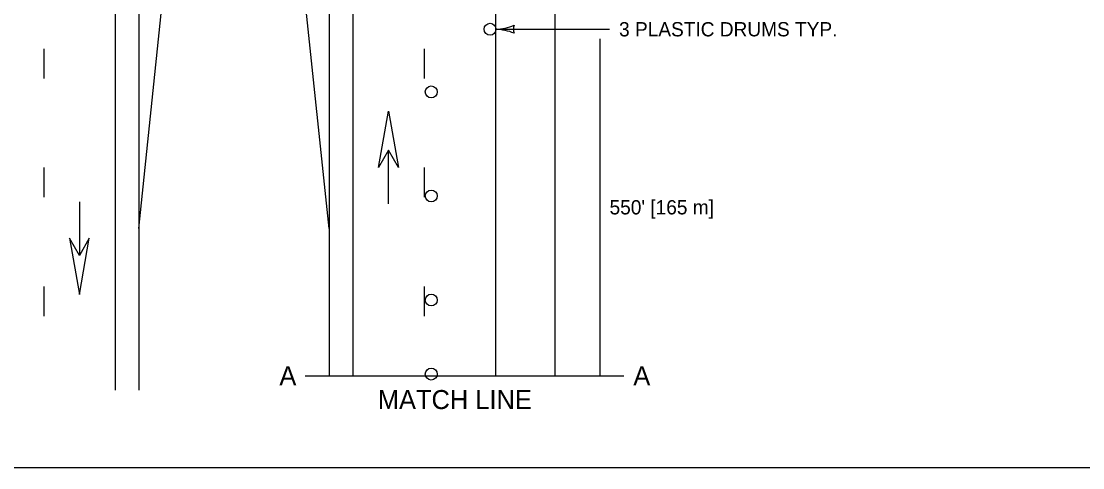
# Model space of a CAD drawing. Extents: x 49991.4 to 50021, y 49987.6 to 50011.4.
# Drawn here: x 50006.491 to 50010.956, y 49987.799 to 49989.676 of the extents above; entities that cross this region are included whole.
import ezdxf

# ---------------------------------------------------------------- set-up
doc = ezdxf.new("R2010")
doc.units = 0
for name, color, linetype in [('Level 1', 7, 'Continuous'), ('Level 2', 7, 'Continuous'), ('Level 3', 7, 'Continuous'), ('Level 6', 7, 'Continuous')]:
    doc.layers.add(name, color=color, linetype=linetype)

msp = doc.modelspace()

# ---------------------------------------------------------------- linework, layer by layer
at = {"layer": 'Level 1'}
for p, q in [((50008.4852, 49998.6725), (50008.4852, 49988.1855)), ((50008.7352, 49998.6725), (50008.7352, 49988.1855)), ((50006.9852, 49988.8042), (50007.3601, 49992.3936)), ((50007.7852, 49988.8042), (50007.4103, 49992.3936)), ((50006.9852, 49990.5193), (50006.9852, 49988.1255)), ((50007.7852, 49990.5187), (50007.7852, 49988.1855)), ((50006.8852, 49990.4015), (50006.8852, 49988.1255)), ((50007.8852, 49989.8382), (50007.8852, 49988.1855)), ((50006.5852, 49989.5607), (50006.5852, 49989.4357)), ((50008.1852, 49989.5607), (50008.1852, 49989.4357)), ((50008.0352, 49988.9078), (50008.0352, 49989.1336)), ((50008.0354, 49988.9078), (50008.0354, 49989.1336)), ((50006.5852, 49989.0607), (50006.5852, 49988.9357)), ((50008.1852, 49989.0607), (50008.1852, 49988.9357)), ((50006.7352, 49988.9171), (50006.7352, 49988.6913)), ((50006.7354, 49988.9171), (50006.7354, 49988.6913)), ((50006.5852, 49988.5607), (50006.5852, 49988.4357)), ((50008.1852, 49988.5607), (50008.1852, 49988.4357))]:
    msp.add_line(p, q, dxfattribs=at)
for points in [[(49999.3835, 49998.9992), (50016.7501, 49998.9992), (50016.7501, 49987.7988), (49999.3835, 49987.7988)], [(50007.9934, 49989.0614), (50008.0352, 49989.2978), (50008.077, 49989.0614), (50008.0352, 49989.1334)], [(50006.6934, 49988.7635), (50006.7352, 49988.5271), (50006.777, 49988.7635), (50006.7352, 49988.6915)]]:
    msp.add_lwpolyline(points, close=True, dxfattribs=at)
for centre in [(50008.4625, 49989.6423), (50008.2151, 49989.3789), (50008.2151, 49988.9414), (50008.2151, 49988.5039), (50008.2151, 49988.1925)]:
    msp.add_circle(centre, 0.025, dxfattribs=at)
at = {"layer": 'Level 3'}
for p, q in [((50008.4875, 49989.6423), (50008.9652, 49989.6423)), ((50008.9252, 49988.1855), (50008.9252, 49989.6023))]:
    msp.add_line(p, q, dxfattribs=at)
for centre, radius, start, end in [((50008.476, 49989.875), 0.233, 272.8273, 292.0772), ((50008.6157, 49989.6423), 0.0548, 162.1388, 197.8612), ((50008.4783, 49989.4202), 0.2223, 67.456, 87.6395)]:
    msp.add_arc(centre, radius, start, end, dxfattribs=at)
at = {"layer": 'Level 6'}
msp.add_line((50007.6852, 49988.1855), (50009.0252, 49988.1855), dxfattribs=at)

# ---------------------------------------------------------------- texts
at = {"layer": 'Level 2'}
for s, height, p in [('3 PLASTIC DRUMS TYP.', 0.06, (50009.0052, 49989.6123)), ("550' [165 m]", 0.06, (50008.9652, 49988.8639)), ('A', 0.08, (50007.5765, 49988.1455)), ('A', 0.08, (50009.0652, 49988.1455)), ('MATCH LINE', 0.08, (50007.9906, 49988.0455))]:
    msp.add_text(s, height=height, dxfattribs=at).set_placement(p)

doc.saveas('drawing.dxf')
